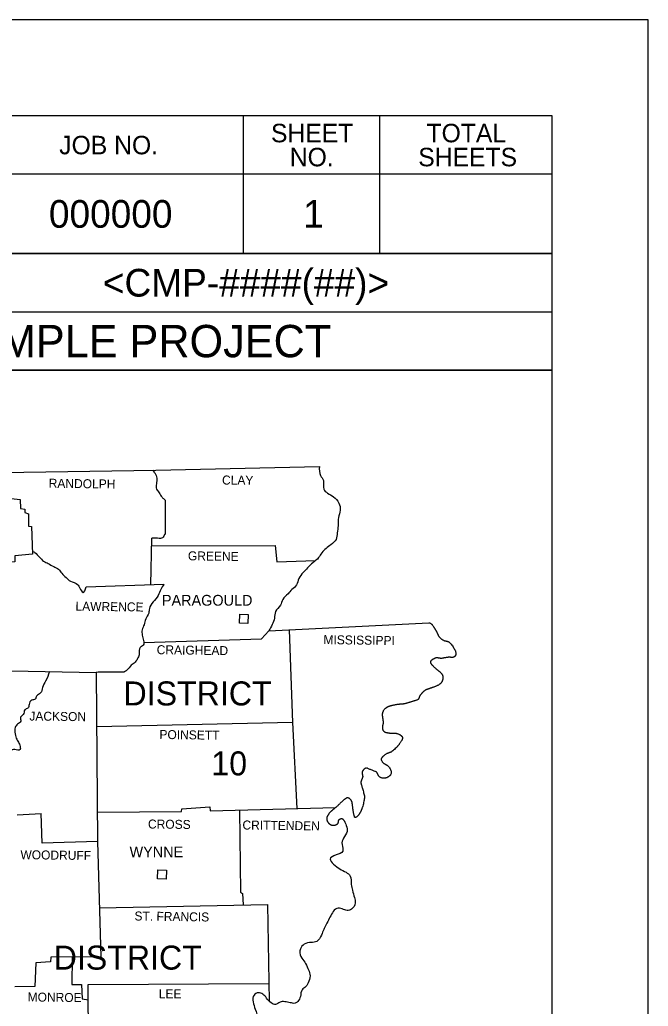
# Model space of a CAD drawing. Extents: x -0.25 to 1.42, y 0 to 0.92.
# Drawn here: x 1.2805 to 1.4167, y 0.703 to 0.9167 of the extents above; entities that cross this region are included whole.
import ezdxf

# ---------------------------------------------------------------- set-up
doc = ezdxf.new("R2010")
doc.units = 0
for name, color, linetype in [('SHET_Annotations', 7, 'Continuous'), ('SHET_Border-Lines', 7, 'Continuous'), ('SHET_Border-Text', 7, 'Continuous')]:
    doc.layers.add(name, color=color, linetype=linetype)

msp = doc.modelspace()

# ---------------------------------------------------------------- linework, layer by layer
at = {"layer": 'SHET_Annotations'}
for p, q in [((1.30981, 0.81849), (1.30946, 0.81908)), ((1.31179, 0.81284), (1.31202, 0.81262)), ((1.31186, 0.80498), (1.31202, 0.80525)), ((1.28383, 0.80129), (1.28329, 0.80145)), ((1.31176, 0.79437), (1.31178, 0.79439)), ((1.27998, 0.74446), (1.28519, 0.74474))]:
    msp.add_line(p, q, dxfattribs=at)
for points in [[(1.09511, 0.81784), (1.16886, 0.81779), (1.23365, 0.81792), (1.31002, 0.81909), (1.34545, 0.81992)], [(1.27561, 0.81856), (1.27545, 0.81717), (1.27636, 0.81704), (1.27628, 0.81652), (1.27735, 0.81628), (1.27742, 0.81553), (1.27794, 0.81522), (1.27807, 0.81304), (1.28066, 0.81278), (1.28069, 0.81079), (1.28165, 0.81068), (1.28162, 0.8099), (1.28245, 0.80965), (1.28243, 0.807), (1.28313, 0.80687), (1.28331, 0.80091), (1.27945, 0.80054), (1.2795, 0.79927), (1.27833, 0.79919), (1.27872, 0.77567), (1.29711, 0.77526), (1.29742, 0.73864), (1.28541, 0.73833), (1.28519, 0.74474)], [(1.31202, 0.81262), (1.31202, 0.80525)], [(1.30892, 0.7943), (1.30914, 0.80435)], [(1.3091, 0.80269), (1.33588, 0.80282), (1.33624, 0.79927), (1.3446, 0.79956)], [(1.29495, 0.79383), (1.31178, 0.79439)], [(1.30741, 0.78176), (1.33287, 0.7826), (1.33448, 0.78431)], [(1.33448, 0.78431), (1.36913, 0.78605)], [(1.33888, 0.78453), (1.33964, 0.76447), (1.34056, 0.74579)], [(1.30307, 0.77533), (1.29752, 0.77536), (1.29711, 0.77526)], [(1.33964, 0.76447), (1.29721, 0.7635)], [(1.29736, 0.74504), (1.31557, 0.74515), (1.31562, 0.74577), (1.32174, 0.74621), (1.32177, 0.74528), (1.34896, 0.74602)], [(1.32812, 0.74545), (1.32838, 0.72769), (1.32877, 0.72741), (1.32894, 0.72492)], [(1.29742, 0.73864), (1.29812, 0.71366), (1.28725, 0.71361), (1.2872, 0.7126), (1.28406, 0.71239), (1.2838, 0.70723), (1.27948, 0.7072)], [(1.29782, 0.72429), (1.33419, 0.72502)], [(1.33419, 0.72502), (1.33457, 0.70412)], [(1.29192, 0.71363), (1.29184, 0.7077), (1.29394, 0.7077), (1.29405, 0.70456), (1.29542, 0.7044)], [(1.29727, 0.6672), (1.30154, 0.66747), (1.30152, 0.67671), (1.29814, 0.67697), (1.29833, 0.69507), (1.29547, 0.69548), (1.2954, 0.70767), (1.3345, 0.70793)]]:
    msp.add_lwpolyline(points, dxfattribs=at)
for points in [[(1.32815, 0.78594), (1.3282, 0.78791), (1.32999, 0.78786), (1.32994, 0.78589)], [(1.31041, 0.73055), (1.31046, 0.73252), (1.31233, 0.73246), (1.31228, 0.73049)]]:
    msp.add_lwpolyline(points, close=True, dxfattribs=at)
for points in [[(1.30981, 0.81849), (1.31023, 0.81737), (1.31015, 0.81613), (1.31018, 0.81501), (1.31075, 0.81421), (1.31137, 0.81325), (1.31179, 0.81284)], [(1.34545, 0.81992), (1.34568, 0.81792), (1.3463, 0.81688), (1.34641, 0.81496), (1.34719, 0.81413), (1.34851, 0.81333), (1.34968, 0.81198), (1.34994, 0.81042), (1.34957, 0.80884), (1.34949, 0.80708), (1.34931, 0.80552), (1.34905, 0.8041), (1.34794, 0.80295), (1.3469, 0.80215), (1.34594, 0.80119), (1.34527, 0.80015), (1.34405, 0.79906), (1.34288, 0.79792), (1.34192, 0.79691), (1.34099, 0.79564), (1.34049, 0.79424), (1.33948, 0.79323), (1.33865, 0.79232), (1.33754, 0.7911), (1.33699, 0.78983), (1.33596, 0.78846), (1.3357, 0.78708), (1.33448, 0.78431)], [(1.31186, 0.80498), (1.31127, 0.80435), (1.3101, 0.80438), (1.30914, 0.80435)], [(1.28383, 0.80129), (1.28481, 0.80026), (1.28572, 0.79938), (1.28671, 0.79888), (1.2879, 0.79821), (1.28894, 0.79764), (1.28964, 0.79678), (1.29057, 0.79582), (1.29153, 0.79507), (1.29306, 0.79434), (1.29355, 0.79357), (1.29425, 0.79261), (1.29495, 0.79383)], [(1.31176, 0.79437), (1.31109, 0.79325), (1.31054, 0.79198), (1.30945, 0.79056), (1.30862, 0.78913), (1.30847, 0.78815), (1.30782, 0.78687), (1.30748, 0.78563), (1.30707, 0.78451), (1.30707, 0.78337), (1.30738, 0.78223), (1.3073, 0.78117), (1.3066, 0.78068), (1.30644, 0.77935), (1.30613, 0.77845), (1.30554, 0.77751), (1.30468, 0.77684), (1.30377, 0.7758), (1.30307, 0.77533)], [(1.28698, 0.77548), (1.28614, 0.77342), (1.28546, 0.77204), (1.28507, 0.77085), (1.28419, 0.77017), (1.28391, 0.76952), (1.28315, 0.76927), (1.28256, 0.76836), (1.2823, 0.76755), (1.28165, 0.76719), (1.28131, 0.76615), (1.28074, 0.76561), (1.28077, 0.7647), (1.28009, 0.76408), (1.27955, 0.76335), (1.27952, 0.76232), (1.27978, 0.76102), (1.28025, 0.76021), (1.28064, 0.75923), (1.28061, 0.75858), (1.27947, 0.75858), (1.27849, 0.75843)], [(1.35126, 0.74211), (1.35144, 0.74082), (1.35064, 0.73939), (1.35035, 0.73799), (1.35051, 0.73656), (1.34905, 0.73578), (1.34776, 0.73485), (1.34851, 0.73379), (1.34986, 0.73275), (1.35123, 0.732), (1.35209, 0.73119), (1.35235, 0.72935), (1.35258, 0.72813), (1.35302, 0.72653), (1.3532, 0.72536), (1.3524, 0.72401), (1.35144, 0.72373), (1.3504, 0.72406), (1.34921, 0.72414), (1.34825, 0.72321), (1.34758, 0.72196), (1.3469, 0.72066), (1.34638, 0.71958), (1.34589, 0.71841), (1.34488, 0.71703), (1.34366, 0.7168), (1.34218, 0.71644), (1.34132, 0.71543), (1.34145, 0.71374), (1.34228, 0.71257), (1.34293, 0.71117), (1.3434, 0.70993), (1.34314, 0.7084), (1.34252, 0.70726), (1.34171, 0.70656), (1.34132, 0.7051), (1.34075, 0.70401), (1.34018, 0.70365), (1.33909, 0.70376), (1.33793, 0.70396), (1.33692, 0.70389), (1.33593, 0.70337), (1.33497, 0.7037), (1.33399, 0.70477), (1.33318, 0.7056), (1.33225, 0.70591), (1.33129, 0.70542), (1.33111, 0.70391), (1.33155, 0.70236), (1.33199, 0.70025), (1.33157, 0.69901), (1.33142, 0.69688)]]:
    msp.add_spline(points, degree=3, dxfattribs=at)
msp.add_open_spline([(1.36913, 0.78605), (1.3693, 0.78602), (1.36947, 0.78595), (1.36962, 0.78584), (1.36978, 0.78572), (1.3699, 0.78558), (1.37001, 0.78543), (1.37012, 0.78526), (1.37024, 0.78509), (1.37034, 0.78492), (1.37039, 0.78483), (1.37045, 0.78474), (1.3705, 0.78466), (1.37055, 0.78458), (1.3706, 0.78449), (1.37066, 0.78441), (1.37073, 0.7843), (1.37079, 0.78419), (1.37085, 0.78407), (1.3709, 0.78395), (1.37095, 0.78383), (1.37101, 0.78371), (1.37106, 0.7836), (1.37112, 0.78348), (1.37117, 0.78336), (1.37123, 0.78325), (1.3713, 0.78314), (1.37138, 0.78304), (1.37165, 0.78271), (1.37197, 0.78246), (1.37234, 0.78226), (1.37243, 0.78221), (1.37253, 0.78217), (1.37263, 0.78214), (1.37273, 0.78212), (1.37283, 0.7821), (1.37293, 0.78208), (1.37303, 0.78206), (1.37314, 0.78204), (1.37324, 0.78201), (1.37334, 0.78198), (1.37343, 0.78194), (1.37351, 0.78187), (1.37388, 0.78158), (1.37414, 0.78123), (1.37439, 0.78083), (1.37463, 0.78046), (1.37483, 0.78009), (1.37496, 0.77967), (1.37499, 0.77958), (1.375, 0.77949), (1.375, 0.77941), (1.375, 0.77932), (1.37499, 0.77923), (1.37497, 0.77913), (1.37494, 0.77904), (1.37491, 0.77896), (1.37486, 0.77888), (1.37483, 0.77884), (1.3748, 0.7788), (1.37477, 0.77877), (1.37475, 0.77875), (1.37473, 0.77874), (1.37471, 0.77872), (1.37469, 0.77871), (1.37467, 0.77869), (1.37465, 0.77868), (1.37455, 0.77862), (1.37444, 0.77858), (1.37433, 0.77856), (1.37422, 0.77855), (1.37411, 0.77855), (1.374, 0.77855), (1.37389, 0.77856), (1.37379, 0.77858), (1.37368, 0.77858), (1.37362, 0.77859), (1.37357, 0.77859), (1.37351, 0.77859), (1.37346, 0.77859), (1.37341, 0.77858), (1.37335, 0.77858), (1.37312, 0.77854), (1.37289, 0.7785), (1.37265, 0.77846), (1.37242, 0.77842), (1.37219, 0.77838), (1.37195, 0.77834), (1.37184, 0.77832), (1.37173, 0.77833), (1.37162, 0.77835), (1.37151, 0.77836), (1.37139, 0.77839), (1.37128, 0.77841), (1.37117, 0.77842), (1.37106, 0.77844), (1.37094, 0.77845), (1.37089, 0.77845), (1.37083, 0.77844), (1.37077, 0.77844), (1.37072, 0.77843), (1.37066, 0.77841), (1.3706, 0.77839), (1.37047, 0.77835), (1.37035, 0.77829), (1.37022, 0.77823), (1.37009, 0.77817), (1.36996, 0.77809), (1.36984, 0.77801), (1.36974, 0.77794), (1.36965, 0.77786), (1.36957, 0.77776), (1.36953, 0.77771), (1.36951, 0.77767), (1.3695, 0.77762), (1.36949, 0.7776), (1.36949, 0.77758), (1.36949, 0.77755), (1.36948, 0.77753), (1.36948, 0.77751), (1.36949, 0.77749), (1.36952, 0.77738), (1.36956, 0.77728), (1.36963, 0.77718), (1.36971, 0.77707), (1.36979, 0.77697), (1.36988, 0.77687), (1.37008, 0.77667), (1.37029, 0.77646), (1.3705, 0.77627), (1.37061, 0.77617), (1.37072, 0.77607), (1.37083, 0.77598), (1.37094, 0.77589), (1.37106, 0.7758), (1.37117, 0.77571), (1.37128, 0.77562), (1.37139, 0.77553), (1.37151, 0.77544), (1.37162, 0.77535), (1.37172, 0.77524), (1.37182, 0.77513), (1.3719, 0.77504), (1.37196, 0.77494), (1.37202, 0.77484), (1.37207, 0.77474), (1.37211, 0.77463), (1.37215, 0.77452), (1.37218, 0.77441), (1.37219, 0.7743), (1.3722, 0.77419), (1.37221, 0.77409), (1.37221, 0.77399), (1.37219, 0.77388), (1.37214, 0.77365), (1.37206, 0.77344), (1.37194, 0.77323), (1.37188, 0.77312), (1.3718, 0.77302), (1.37172, 0.77293), (1.37163, 0.77284), (1.37154, 0.77276), (1.37143, 0.77269), (1.37121, 0.77255), (1.37097, 0.77242), (1.37073, 0.77232), (1.37049, 0.77223), (1.37025, 0.77213), (1.37001, 0.77204), (1.36989, 0.772), (1.36977, 0.77195), (1.36965, 0.77191), (1.36952, 0.77187), (1.3694, 0.77183), (1.36928, 0.77179), (1.36916, 0.77175), (1.36904, 0.77171), (1.36891, 0.77167), (1.36879, 0.77163), (1.36867, 0.77158), (1.36856, 0.77152), (1.36843, 0.77146), (1.36831, 0.77139), (1.3682, 0.7713), (1.36809, 0.77122), (1.36798, 0.77113), (1.36788, 0.77103), (1.36778, 0.77093), (1.36769, 0.77082), (1.36759, 0.77072), (1.3675, 0.77062), (1.3674, 0.77051), (1.36731, 0.77041), (1.36724, 0.77033), (1.36719, 0.77024), (1.36715, 0.77014), (1.36711, 0.77004), (1.36708, 0.76994), (1.36704, 0.76984), (1.367, 0.76974), (1.36696, 0.76965), (1.36691, 0.76956), (1.36685, 0.76948), (1.36678, 0.76941), (1.36669, 0.76937), (1.36646, 0.76927), (1.36623, 0.76918), (1.36599, 0.76911), (1.36576, 0.76904), (1.36552, 0.76897), (1.36529, 0.7689), (1.36505, 0.76883), (1.36481, 0.76875), (1.36457, 0.76868), (1.36432, 0.76861), (1.36408, 0.76854), (1.36384, 0.76849), (1.36373, 0.76846), (1.36362, 0.76845), (1.36351, 0.76844), (1.36341, 0.76843), (1.3633, 0.76842), (1.36319, 0.76841), (1.36308, 0.7684), (1.36297, 0.7684), (1.36286, 0.76839), (1.36276, 0.76838), (1.36265, 0.76837), (1.36254, 0.76836), (1.3623, 0.76833), (1.36206, 0.76829), (1.36182, 0.76824), (1.36159, 0.7682), (1.36135, 0.76815), (1.36111, 0.7681), (1.36098, 0.76807), (1.36085, 0.76804), (1.36073, 0.768), (1.3606, 0.76796), (1.36048, 0.76791), (1.36036, 0.76786), (1.36023, 0.7678), (1.36012, 0.76774), (1.36, 0.76766), (1.35994, 0.76763), (1.35989, 0.76758), (1.35983, 0.76754), (1.35977, 0.7675), (1.35972, 0.76745), (1.35966, 0.7674), (1.35949, 0.76724), (1.35934, 0.76705), (1.35922, 0.76684), (1.35917, 0.76674), (1.35913, 0.76664), (1.35911, 0.76653), (1.35908, 0.76642), (1.35906, 0.76631), (1.35906, 0.76621), (1.35906, 0.76607), (1.35907, 0.76592), (1.35908, 0.76578), (1.3591, 0.76564), (1.35912, 0.7655), (1.35914, 0.76536), (1.35916, 0.76522), (1.35918, 0.76508), (1.3592, 0.76494), (1.35922, 0.7648), (1.35924, 0.76466), (1.35925, 0.76452), (1.35925, 0.76437), (1.35923, 0.76423), (1.35921, 0.76408), (1.35919, 0.76393), (1.35914, 0.76379), (1.35912, 0.76364), (1.35909, 0.76349), (1.35908, 0.76334), (1.35908, 0.76319), (1.35909, 0.76312), (1.3591, 0.76305), (1.35912, 0.76297), (1.35913, 0.76294), (1.35915, 0.7629), (1.35916, 0.76287), (1.35918, 0.76283), (1.3592, 0.76279), (1.35922, 0.76276), (1.35929, 0.76263), (1.35939, 0.76253), (1.35951, 0.76245), (1.35963, 0.76237), (1.35976, 0.76232), (1.35989, 0.76229), (1.36003, 0.76226), (1.36017, 0.76224), (1.36031, 0.76222), (1.36045, 0.7622), (1.36058, 0.76218), (1.36072, 0.76216), (1.36083, 0.76215), (1.36094, 0.76213), (1.36105, 0.76213), (1.36116, 0.76213), (1.36127, 0.76214), (1.36138, 0.76214), (1.3615, 0.76214), (1.36161, 0.76214), (1.36172, 0.76214), (1.36183, 0.76214), (1.36194, 0.76213), (1.36205, 0.76211), (1.36229, 0.76206), (1.36253, 0.76198), (1.36275, 0.76187), (1.36287, 0.76182), (1.36297, 0.76175), (1.36307, 0.76167), (1.36312, 0.76164), (1.36317, 0.76159), (1.36321, 0.76155), (1.36326, 0.76151), (1.3633, 0.76146), (1.36334, 0.76141), (1.3634, 0.76134), (1.36343, 0.76125), (1.36344, 0.76117), (1.36346, 0.76108), (1.36345, 0.76099), (1.36342, 0.7609), (1.36336, 0.76072), (1.36329, 0.76055), (1.36319, 0.7604), (1.36304, 0.76018), (1.3629, 0.75996), (1.36274, 0.75976), (1.36266, 0.75965), (1.36258, 0.75955), (1.36249, 0.75945), (1.36241, 0.75935), (1.36232, 0.75925), (1.36223, 0.75915), (1.36189, 0.75878), (1.36152, 0.75844), (1.36111, 0.75814), (1.36103, 0.75808), (1.36094, 0.75803), (1.36084, 0.75799), (1.36075, 0.75795), (1.36065, 0.75792), (1.36055, 0.75788), (1.36046, 0.75785), (1.36036, 0.75782), (1.36026, 0.75778), (1.36016, 0.75775), (1.36006, 0.7577), (1.35997, 0.75765), (1.35975, 0.75752), (1.35955, 0.75737), (1.35935, 0.75721), (1.35925, 0.75713), (1.35917, 0.75705), (1.35909, 0.75696), (1.35901, 0.75688), (1.35894, 0.75679), (1.35888, 0.75669), (1.35881, 0.75655), (1.35884, 0.75635), (1.35891, 0.7562), (1.359, 0.75603), (1.3591, 0.75586), (1.35925, 0.75573), (1.35932, 0.75566), (1.35939, 0.75559), (1.35948, 0.75554), (1.35957, 0.7555), (1.35966, 0.75545), (1.35974, 0.7554), (1.35983, 0.75536), (1.35991, 0.75531), (1.36, 0.75526), (1.36009, 0.75522), (1.36016, 0.75515), (1.36023, 0.75508), (1.36054, 0.75478), (1.36076, 0.75442), (1.36091, 0.75404), (1.36102, 0.75375), (1.36102, 0.75335), (1.36083, 0.75308), (1.36079, 0.75303), (1.36075, 0.75299), (1.36071, 0.75295), (1.36067, 0.7529), (1.36063, 0.75286), (1.36058, 0.75283), (1.3605, 0.75275), (1.36041, 0.75269), (1.36032, 0.75263), (1.36014, 0.75252), (1.35994, 0.75246), (1.35974, 0.75241), (1.35954, 0.75236), (1.35932, 0.75237), (1.35912, 0.7524), (1.35891, 0.75244), (1.35871, 0.75251), (1.35852, 0.75264), (1.35841, 0.75272), (1.35833, 0.7528), (1.35827, 0.75291), (1.35821, 0.75302), (1.35816, 0.75313), (1.3581, 0.75324), (1.35804, 0.75335), (1.35799, 0.75346), (1.35792, 0.75356), (1.35786, 0.75366), (1.35777, 0.75374), (1.35766, 0.75378), (1.35734, 0.75393), (1.357, 0.75404), (1.35668, 0.75417), (1.35638, 0.75429), (1.35609, 0.75444), (1.3558, 0.75456), (1.35571, 0.75459), (1.35562, 0.7546), (1.35553, 0.75458), (1.35544, 0.75455), (1.35535, 0.75451), (1.35527, 0.75445), (1.35518, 0.75438), (1.3551, 0.75432), (1.35503, 0.75424), (1.35499, 0.75419), (1.35495, 0.75415), (1.35491, 0.7541), (1.35488, 0.75406), (1.35484, 0.75401), (1.35481, 0.75396), (1.35475, 0.75387), (1.3547, 0.75375), (1.35469, 0.75364), (1.35469, 0.75353), (1.3547, 0.75342), (1.35472, 0.75331), (1.35475, 0.7532), (1.35478, 0.7531), (1.3548, 0.75299), (1.35481, 0.75293), (1.35481, 0.75288), (1.35482, 0.75283), (1.35482, 0.75277), (1.35482, 0.75272), (1.35481, 0.75267), (1.35479, 0.75254), (1.35475, 0.75243), (1.35471, 0.75231), (1.35466, 0.75219), (1.3546, 0.75207), (1.35456, 0.75195), (1.35451, 0.75184), (1.35447, 0.75172), (1.35444, 0.7516), (1.35442, 0.75148), (1.35442, 0.75136), (1.35445, 0.75124), (1.35455, 0.75089), (1.35466, 0.75053), (1.35476, 0.75018), (1.35489, 0.7497), (1.35503, 0.74923), (1.35515, 0.74875), (1.35523, 0.7484), (1.35518, 0.74802), (1.35512, 0.74766), (1.35503, 0.74713), (1.35492, 0.7466), (1.35476, 0.74608), (1.35471, 0.74594), (1.35467, 0.7458), (1.35461, 0.74566), (1.35455, 0.74552), (1.35449, 0.74539), (1.35443, 0.74526), (1.35436, 0.74512), (1.35429, 0.74499), (1.35421, 0.74486), (1.35414, 0.74473), (1.35406, 0.7446), (1.35398, 0.74447), (1.35386, 0.74428), (1.35369, 0.74414), (1.3535, 0.74399), (1.35341, 0.74393), (1.35332, 0.7439), (1.35323, 0.74388), (1.3532, 0.74387), (1.35317, 0.74387), (1.35313, 0.7439), (1.3531, 0.74392), (1.35308, 0.74395), (1.35307, 0.74398), (1.35299, 0.74426), (1.35291, 0.74455), (1.35286, 0.74484), (1.35281, 0.74513), (1.35275, 0.74542), (1.35271, 0.74572), (1.35268, 0.74595), (1.35265, 0.74618), (1.35262, 0.74642), (1.35261, 0.74653), (1.3526, 0.74665), (1.35258, 0.74677), (1.35257, 0.74689), (1.35255, 0.747), (1.35253, 0.74712), (1.35251, 0.7472), (1.35249, 0.74728), (1.35246, 0.74735), (1.35242, 0.74743), (1.35239, 0.7475), (1.35234, 0.74757), (1.35229, 0.74764), (1.35224, 0.7477), (1.35218, 0.74777), (1.35212, 0.74783), (1.35206, 0.74789), (1.35198, 0.74795), (1.35187, 0.74804), (1.35174, 0.74809), (1.3516, 0.7481), (1.35148, 0.74812), (1.35134, 0.74809), (1.35123, 0.74803), (1.35115, 0.74797), (1.35107, 0.74792), (1.35099, 0.74786), (1.35091, 0.7478), (1.35083, 0.74775), (1.35075, 0.74768), (1.35059, 0.74756), (1.35044, 0.74744), (1.3503, 0.7473), (1.35012, 0.74713), (1.34994, 0.74695), (1.34977, 0.74678), (1.34959, 0.74661), (1.34941, 0.74643), (1.34923, 0.74626), (1.34913, 0.74616), (1.34902, 0.74607), (1.34891, 0.74598), (1.3488, 0.74589), (1.34869, 0.7458), (1.34858, 0.74571), (1.34847, 0.74562), (1.34836, 0.74553), (1.34824, 0.74544), (1.34813, 0.74534), (1.34802, 0.74525), (1.34791, 0.74515), (1.34773, 0.74498), (1.34758, 0.74479), (1.34744, 0.74459), (1.34737, 0.74449), (1.34731, 0.74439), (1.34726, 0.74429), (1.3472, 0.74419), (1.34715, 0.74409), (1.34711, 0.74398), (1.34706, 0.74387), (1.34704, 0.74375), (1.34703, 0.74364), (1.34703, 0.74351), (1.34704, 0.74339), (1.34709, 0.74327), (1.34713, 0.74313), (1.34718, 0.74301), (1.34726, 0.7429), (1.3473, 0.74283), (1.34734, 0.74278), (1.34739, 0.74272), (1.34741, 0.74269), (1.34744, 0.74266), (1.34747, 0.74263), (1.34749, 0.74261), (1.34752, 0.74258), (1.34755, 0.74255), (1.34763, 0.74248), (1.34771, 0.74242), (1.3478, 0.74237), (1.34788, 0.74232), (1.34797, 0.74228), (1.34805, 0.74225), (1.34814, 0.74223), (1.34822, 0.74221), (1.34831, 0.7422), (1.34839, 0.74219), (1.34848, 0.74219), (1.34856, 0.74219), (1.34863, 0.74219), (1.34869, 0.7422), (1.34876, 0.74221), (1.34882, 0.74223), (1.34889, 0.74225), (1.34895, 0.74227), (1.34902, 0.7423), (1.34908, 0.74233), (1.34914, 0.74236), (1.34921, 0.74239), (1.34928, 0.74243), (1.34934, 0.74248), (1.34941, 0.74253), (1.34947, 0.7426), (1.3495, 0.74268), (1.34953, 0.74276), (1.34955, 0.74285), (1.34956, 0.74294), (1.34958, 0.74302), (1.34959, 0.74311), (1.34961, 0.7432), (1.34963, 0.74328), (1.34967, 0.74335), (1.34973, 0.74341), (1.34978, 0.74346), (1.34984, 0.7435), (1.3499, 0.74353), (1.34997, 0.74357), (1.35005, 0.74359), (1.35012, 0.74361), (1.35019, 0.74363), (1.35027, 0.74364), (1.35034, 0.74363), (1.3504, 0.74361), (1.35046, 0.74359), (1.35051, 0.74354), (1.35055, 0.74349), (1.35059, 0.74344), (1.35063, 0.74338), (1.35067, 0.74333), (1.35071, 0.74327), (1.35075, 0.74322), (1.35082, 0.74311), (1.35089, 0.74299), (1.35095, 0.74287), (1.35108, 0.74263), (1.35117, 0.74237), (1.35126, 0.74211)], degree=3, dxfattribs=at)
at = {"layer": 'SHET_Border-Lines'}
for p, q in [((1.32894, 0.89583), (1.32894, 0.86601)), ((1.35843, 0.89583), (1.35843, 0.86601)), ((1.39583, 0.8832), (1.21266, 0.8832)), ((1.39583, 0.88329), (1.39583, 0.88329)), ((1.39583, 0.86601), (1.21266, 0.86601)), ((1.22524, 0.86601), (1.39583, 0.86601)), ((1.21266, 0.85338), (1.39583, 0.85338)), ((1.39583, 0.84075), (1.21266, 0.84075))]:
    msp.add_line(p, q, dxfattribs=at)
for points in [[(0, 0), (1.41667, 0), (1.41667, 0.91667), (0, 0.91667)], [(0.02083, 0.02083), (1.39583, 0.02083), (1.39583, 0.89583), (0.02083, 0.89583)], [(1.04658, 0.85338), (1.21266, 0.85338), (1.21266, 0.84075), (1.39583, 0.84075), (1.39583, 0.89583), (1.04658, 0.89583)]]:
    msp.add_lwpolyline(points, close=True, dxfattribs=at)

# ---------------------------------------------------------------- texts
at = {"layer": 'SHET_Annotations'}
for s, height, p in [('000000', 0.006, (1.28686, 0.87161)), ('1', 0.006, (1.34195, 0.87161)), ('<CMP-####(##)>', 0.006, (1.29855, 0.8567)), ('SAMPLE PROJECT', 0.007, (1.26374, 0.84356)), ('PARAGOULD', 0.002334, (1.31134, 0.78975)), ('DISTRICT', 0.005203, (1.30302, 0.76814)), ('10', 0.005203, (1.32204, 0.75299)), ('WYNNE', 0.002334, (1.30433, 0.73524)), ('DISTRICT', 0.005203, (1.2879, 0.71092))]:
    msp.add_text(s, height=height, dxfattribs=at).set_placement(p)
for s, height, rotation, p in [('RANDOLPH', 0.001945, 359.2573, (1.28681, 0.8153)), ('CLAY', 0.001945, 359.3364, (1.32435, 0.816)), ('GREENE', 0.001945, 359.2711, (1.31696, 0.79958)), ('LAWRENCE', 0.001945, 359.2655, (1.29261, 0.78867)), ('MISSISSIPPI', 0.0019451, 359.2098, (1.34631, 0.78143)), ('CRAIGHEAD', 0.001945, 359.1888, (1.3102, 0.77925)), ('JACKSON', 0.001945, 359.2575, (1.28262, 0.76488)), ('POINSETT', 0.001945, 359.1979, (1.31079, 0.76089)), ('CROSS', 0.001945, 359.3097, (1.30831, 0.74149)), ('CRITTENDEN', 0.001945, 359.2782, (1.32877, 0.74128)), ('WOODRUFF', 0.001945, 359.2708, (1.28068, 0.73485)), ('ST. FRANCIS', 0.0019451, 359.1956, (1.30538, 0.72157)), ('MONROE', 0.001945, 359.1697, (1.28224, 0.70404)), ('LEE', 0.001945, 359.3634, (1.31065, 0.70474))]:
    msp.add_text(s, height=height, rotation=rotation, dxfattribs=at).set_placement(p)
at = {"layer": 'SHET_Border-Text'}
for s, p in [('SHEET', (1.33496, 0.89012)), ('TOTAL', (1.36864, 0.89012)), ('JOB NO.', (1.2891, 0.88752)), ('NO.', (1.33903, 0.88492)), ('SHEETS', (1.36685, 0.88492))]:
    msp.add_text(s, height=0.004, dxfattribs=at).set_placement(p)

doc.saveas('drawing.dxf')
